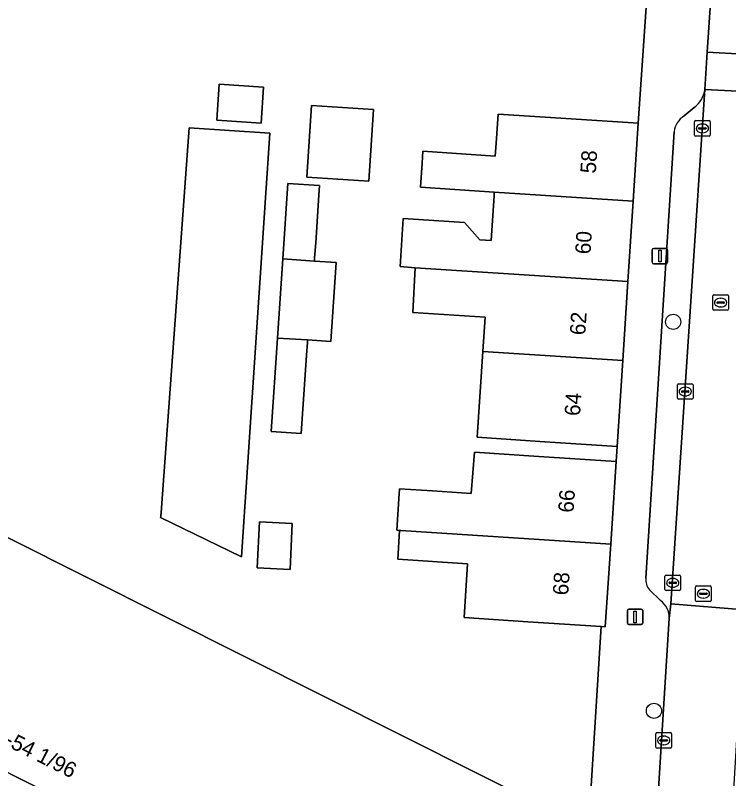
# Model space of a CAD drawing. Extents: x 160349 to 161355, y 381727 to 382854.
# Drawn here: x 160480.68 to 160526.67, y 382016.9 to 382066.09 of the extents above; entities that cross this region are included whole.
import ezdxf

# ---------------------------------------------------------------- set-up
doc = ezdxf.new("R2010")
doc.units = 0
for name, color, linetype in [('IMGEO_Boom', 7, 'Continuous'), ('IMGEO_Erf', 7, 'Continuous'), ('IMGEO_Kolk', 7, 'Continuous'), ('IMGEO_Lichtmast', 7, 'Continuous'), ('IMGEO_Pand', 7, 'Continuous'), ('IMGEO_Pand_nummerreeks', 7, 'Continuous'), ('IMGEO_Parkeervlak_open', 7, 'Continuous'), ('IMGEO_Rijbaan_lokaal_open', 7, 'Continuous'), ('IMGEO_Rioolput', 7, 'Continuous'), ('IMGEO_Voetpad_open', 7, 'Continuous')]:
    doc.layers.add(name, color=color, linetype=linetype)

msp = doc.modelspace()

# ---------------------------------------------------------------- linework, layer by layer
at = {"layer": 'IMGEO_Boom'}
for centre in [(160523.087, 382046.336), (160521.848, 382021.271)]:
    msp.add_circle(centre, 0.489, dxfattribs=at)
at = {"layer": 'IMGEO_Erf'}
msp.add_lwpolyline([(160517.469, 382011.278), (160518.446, 382026.709), (160513.722, 382027.017), (160509.607, 382027.278), (160509.82, 382030.754), (160505.333, 382031.047), (160505.456, 382032.902), (160505.273, 382032.914), (160505.426, 382035.282), (160505.442, 382035.525), (160505.446, 382035.586), (160507.584, 382035.446), (160510.075, 382035.283), (160510.286, 382037.948), (160514.417, 382037.667), (160519.406, 382037.341), (160519.474, 382038.309), (160514.485, 382038.635), (160510.455, 382038.898), (160510.816, 382044.432), (160510.96, 382046.638), (160506.3, 382046.943), (160506.464, 382049.826), (160505.491, 382049.898), (160505.694, 382052.997), (160509.639, 382052.739), (160510.616, 382051.626), (160511.351, 382051.578), (160511.539, 382054.465), (160511.554, 382054.702), (160506.797, 382055.012), (160506.898, 382056.555), (160506.948, 382057.327), (160511.622, 382057.02), (160511.676, 382057.846), (160511.799, 382059.731), (160515.844, 382059.467), (160520.833, 382059.141), (160521.557, 382069.746)], dxfattribs=at)
for points in [[(160479.916, 382059.863), (160466.35, 382032.89), (160472.463, 382029.821), (160475.062, 382034.999), (160515.732, 382014.582), (160512.424, 382007.997), (160513.909, 382007.227), (160510.392, 382000.227), (160508.55, 382001.159), (160509.315, 382002.675), (160460.202, 382027.329), (160459.424, 382025.758), (160454.11, 382028.419), (160455.535, 382031.265), (160457.345, 382034.882), (160453.202, 382036.961), (160467.763, 382065.943), (160466.417, 382066.617), (160467.478, 382068.699), (160475.537, 382064.67), (160474.49, 382062.578)], [(160496.69, 382061.467), (160496.533, 382059.132), (160493.675, 382059.324), (160493.832, 382061.659)], [(160503.771, 382060.023), (160503.47, 382055.395), (160499.47, 382055.654), (160499.771, 382060.283)], [(160497.082, 382058.494), (160495.27, 382031.193), (160495.214, 382031.22), (160490.053, 382033.734), (160490.059, 382033.81), (160490.077, 382034.058), (160491.886, 382058.843)], [(160497.929, 382050.391), (160498.261, 382055.25), (160500.299, 382055.124), (160500.257, 382054.512), (160500.047, 382051.439), (160499.98, 382050.456), (160499.966, 382050.258), (160501.368, 382050.167), (160501.019, 382045.071), (160499.524, 382045.169), (160499.512, 382045.003), (160499.457, 382044.2), (160499.111, 382039.145), (160497.168, 382039.271), (160497.58, 382045.296)], [(160496.422, 382033.455), (160498.54, 382033.353), (160498.396, 382030.379), (160496.279, 382030.481)]]:
    msp.add_lwpolyline(points, close=True, dxfattribs=at)
at = {"layer": 'IMGEO_Kolk'}
for p, q in [((160524.543, 382059.304), (160525.395, 382059.304)), ((160524.468, 382058.378), (160524.468, 382059.23)), ((160524.77, 382058.847), (160525.168, 382058.847)), ((160524.956, 382059.084), (160524.981, 382059.084)), ((160525.469, 382059.23), (160525.469, 382058.378)), ((160524.727, 382058.798), (160524.727, 382058.81)), ((160525.165, 382058.761), (160524.767, 382058.761)), ((160524.979, 382058.524), (160524.954, 382058.524)), ((160525.211, 382058.81), (160525.211, 382058.798)), ((160525.395, 382058.304), (160524.543, 382058.304)), ((160523.362, 382041.421), (160523.362, 382042.273)), ((160523.437, 382042.347), (160524.289, 382042.347)), ((160523.85, 382042.127), (160523.875, 382042.127)), ((160524.363, 382042.273), (160524.363, 382041.421)), ((160523.621, 382041.841), (160523.621, 382041.853)), ((160524.059, 382041.804), (160523.661, 382041.804)), ((160523.664, 382041.89), (160524.062, 382041.89)), ((160524.105, 382041.853), (160524.105, 382041.841)), ((160524.289, 382041.347), (160523.437, 382041.347)), ((160523.873, 382041.567), (160523.848, 382041.567)), ((160522.557, 382029.095), (160522.557, 382029.947)), ((160522.632, 382030.021), (160523.484, 382030.021)), ((160523.045, 382029.801), (160523.07, 382029.801)), ((160523.558, 382029.947), (160523.558, 382029.095)), ((160522.816, 382029.515), (160522.816, 382029.527)), ((160523.254, 382029.478), (160522.856, 382029.478)), ((160522.859, 382029.564), (160523.257, 382029.564)), ((160523.3, 382029.527), (160523.3, 382029.515)), ((160523.484, 382029.021), (160522.632, 382029.021)), ((160523.068, 382029.241), (160523.043, 382029.241)), ((160521.975, 382018.94), (160521.975, 382019.792)), ((160522.05, 382019.866), (160522.902, 382019.866)), ((160522.463, 382019.646), (160522.488, 382019.646)), ((160522.976, 382019.792), (160522.976, 382018.94)), ((160522.234, 382019.36), (160522.234, 382019.372)), ((160522.672, 382019.323), (160522.274, 382019.323)), ((160522.277, 382019.409), (160522.675, 382019.409)), ((160522.486, 382019.086), (160522.461, 382019.086)), ((160522.718, 382019.372), (160522.718, 382019.36)), ((160522.902, 382018.866), (160522.05, 382018.866))]:
    msp.add_line(p, q, dxfattribs=at)
for points in [[(160524.543, 382059.304), (160525.395, 382059.304)], [(160524.468, 382058.378), (160524.468, 382059.23)], [(160525.469, 382059.23), (160525.469, 382058.378)], [(160525.395, 382058.304), (160524.543, 382058.304)], [(160523.362, 382041.421), (160523.362, 382042.273)], [(160523.437, 382042.347), (160524.289, 382042.347)], [(160524.363, 382042.273), (160524.363, 382041.421)], [(160524.289, 382041.347), (160523.437, 382041.347)], [(160522.557, 382029.095), (160522.557, 382029.947)], [(160522.632, 382030.021), (160523.484, 382030.021)], [(160523.558, 382029.947), (160523.558, 382029.095)], [(160523.484, 382029.021), (160522.632, 382029.021)], [(160521.975, 382018.94), (160521.975, 382019.792)], [(160522.05, 382019.866), (160522.902, 382019.866)], [(160522.976, 382019.792), (160522.976, 382018.94)], [(160522.902, 382018.866), (160522.05, 382018.866)]]:
    msp.add_lwpolyline(points, dxfattribs=at)
for centre, radius, start, end in [((160524.545, 382059.228), 0.0765, 91.552, 178.448), ((160524.545, 382059.228), 0.0765, 91.552, 178.448), ((160525.393, 382059.228), 0.0765, 1.552, 88.448), ((160525.393, 382059.228), 0.0765, 1.552, 88.448), ((160524.767, 382058.807), 0.0403, 85.8775, 175.7526), ((160525.172, 382058.809), 0.0386, 1.7309, 96.639), ((160524.545, 382058.38), 0.0765, 181.552, 268.448), ((160524.545, 382058.38), 0.0765, 181.552, 268.448), ((160524.764, 382058.797), 0.0366, 178.938, 274.7102), ((160525.168, 382058.804), 0.043, 264.8664, 352.4533), ((160525.393, 382058.38), 0.0765, 271.552, 358.448), ((160525.393, 382058.38), 0.0765, 271.552, 358.448), ((160523.439, 382042.271), 0.0765, 91.552, 178.448), ((160523.439, 382042.271), 0.0765, 91.552, 178.448), ((160524.287, 382042.271), 0.0765, 1.552, 88.448), ((160524.287, 382042.271), 0.0765, 1.552, 88.448), ((160523.661, 382041.85), 0.0403, 85.8775, 175.7526), ((160523.658, 382041.84), 0.0366, 178.938, 274.7102), ((160524.062, 382041.847), 0.043, 264.8664, 352.4533), ((160524.066, 382041.852), 0.0386, 1.7309, 96.639), ((160523.439, 382041.423), 0.0765, 181.552, 268.448), ((160523.439, 382041.423), 0.0765, 181.552, 268.448), ((160524.287, 382041.423), 0.0765, 271.552, 358.448), ((160524.287, 382041.423), 0.0765, 271.552, 358.448), ((160522.634, 382029.945), 0.0765, 91.552, 178.448), ((160522.634, 382029.945), 0.0765, 91.552, 178.448), ((160523.482, 382029.945), 0.0765, 1.552, 88.448), ((160523.482, 382029.945), 0.0765, 1.552, 88.448), ((160522.856, 382029.524), 0.0403, 85.8775, 175.7526), ((160522.853, 382029.514), 0.0366, 178.938, 274.7102), ((160523.257, 382029.521), 0.043, 264.8664, 352.4533), ((160523.261, 382029.526), 0.0386, 1.7309, 96.639), ((160522.634, 382029.097), 0.0765, 181.552, 268.448), ((160522.634, 382029.097), 0.0765, 181.552, 268.448), ((160523.482, 382029.097), 0.0765, 271.552, 358.448), ((160523.482, 382029.097), 0.0765, 271.552, 358.448), ((160522.052, 382019.79), 0.0765, 91.552, 178.448), ((160522.052, 382019.79), 0.0765, 91.552, 178.448), ((160522.9, 382019.79), 0.0765, 1.552, 88.448), ((160522.9, 382019.79), 0.0765, 1.552, 88.448), ((160522.274, 382019.369), 0.0403, 85.8775, 175.7526), ((160522.271, 382019.359), 0.0366, 178.938, 274.7102), ((160522.675, 382019.366), 0.043, 264.8664, 352.4533), ((160522.679, 382019.371), 0.0386, 1.7309, 96.639), ((160522.052, 382018.942), 0.0765, 181.552, 268.448), ((160522.052, 382018.942), 0.0765, 181.552, 268.448), ((160522.9, 382018.942), 0.0765, 271.552, 358.448), ((160522.9, 382018.942), 0.0765, 271.552, 358.448)]:
    msp.add_arc(centre, radius, start, end, dxfattribs=at)
for centre, major_axis, ratio, start_param, end_param in [((160524.955, 382058.804), (-0.387, 0.002), 0.722429, 4.712389, 7.853982), ((160524.98, 382058.804), (-0.39, 0.002), 0.717154, 1.570796, 4.712389), ((160523.849, 382041.847), (-0.387, 0.002), 0.722429, 4.712389, 7.853982), ((160523.874, 382041.847), (-0.39, 0.002), 0.717154, 1.570796, 4.712389), ((160523.044, 382029.521), (-0.387, 0.002), 0.722429, 4.712389, 7.853982), ((160523.069, 382029.521), (-0.39, 0.002), 0.717154, 1.570796, 4.712389), ((160522.462, 382019.366), (-0.387, 0.002), 0.722429, 4.712389, 7.853982), ((160522.487, 382019.366), (-0.39, 0.002), 0.717154, 1.570796, 4.712389)]:
    msp.add_ellipse(centre, major_axis=major_axis, ratio=ratio, start_param=start_param, end_param=end_param, dxfattribs=at)
at = {"layer": 'IMGEO_Lichtmast'}
for p, q in [((160521.732, 382050.174), (160521.732, 382050.974)), ((160521.732, 382050.974), (160521.732, 382050.174)), ((160521.832, 382051.074), (160522.622, 382051.074)), ((160522.622, 382051.074), (160521.832, 382051.074)), ((160522.722, 382050.974), (160522.722, 382050.174)), ((160522.722, 382050.174), (160522.722, 382050.974)), ((160522.622, 382050.074), (160521.832, 382050.074)), ((160521.832, 382050.074), (160522.622, 382050.074)), ((160520.234, 382027.828), (160521.024, 382027.828)), ((160521.024, 382027.828), (160520.234, 382027.828)), ((160520.134, 382026.928), (160520.134, 382027.728)), ((160520.134, 382027.728), (160520.134, 382026.928)), ((160521.124, 382027.728), (160521.124, 382026.928)), ((160521.124, 382026.928), (160521.124, 382027.728)), ((160521.024, 382026.828), (160520.234, 382026.828)), ((160520.234, 382026.828), (160521.024, 382026.828))]:
    msp.add_line(p, q, dxfattribs=at)
for points in [[(160522.152, 382050.949), (160522.302, 382050.949), (160522.302, 382050.199), (160522.152, 382050.199), (160522.152, 382050.949)], [(160520.554, 382027.703), (160520.704, 382027.703), (160520.704, 382026.953), (160520.554, 382026.953), (160520.554, 382027.703)]]:
    msp.add_lwpolyline(points, dxfattribs=at)
for centre, start, end in [((160521.832, 382050.974), 90, 180), ((160521.832, 382050.974), 90, 180), ((160522.622, 382050.974), 0, 90), ((160522.622, 382050.974), 360, 90), ((160521.832, 382050.174), 180, 270), ((160521.832, 382050.174), 180, 270), ((160522.622, 382050.174), 270, 0), ((160522.622, 382050.174), 270, 0), ((160520.234, 382027.728), 90, 180), ((160520.234, 382027.728), 90, 180), ((160521.024, 382027.728), 0, 90), ((160521.024, 382027.728), 360, 90), ((160520.234, 382026.928), 180, 270), ((160520.234, 382026.928), 180, 270), ((160521.024, 382026.928), 270, 0), ((160521.024, 382026.928), 270, 0)]:
    msp.add_arc(centre, 0.1, start, end, dxfattribs=at)
at = {"layer": 'IMGEO_Pand'}
for points in [[(160475.062, 382034.999), (160472.463, 382029.821), (160466.35, 382032.89), (160479.916, 382059.863), (160474.49, 382062.578), (160467.763, 382065.943), (160453.202, 382036.961), (160457.345, 382034.882), (160455.535, 382031.265), (160454.11, 382028.419), (160459.424, 382025.758), (160460.202, 382027.329), (160509.315, 382002.675), (160509.662, 382002.5), (160512.424, 382007.997), (160515.732, 382014.582)], [(160496.69, 382061.467), (160493.832, 382061.659), (160493.675, 382059.324), (160496.533, 382059.132)], [(160503.771, 382060.023), (160499.771, 382060.283), (160499.47, 382055.654), (160503.47, 382055.395)], [(160520.833, 382059.141), (160515.844, 382059.467), (160511.799, 382059.731), (160511.676, 382057.846), (160511.622, 382057.02), (160506.948, 382057.327), (160506.898, 382056.555), (160506.797, 382055.012), (160511.554, 382054.702), (160520.505, 382054.118)], [(160490.059, 382033.81), (160490.053, 382033.734), (160495.214, 382031.22), (160495.27, 382031.193), (160497.082, 382058.494), (160491.886, 382058.843), (160490.077, 382034.058)], [(160497.929, 382050.391), (160499.966, 382050.258), (160499.98, 382050.456), (160500.047, 382051.439), (160500.257, 382054.512), (160500.299, 382055.124), (160498.261, 382055.25)], [(160520.505, 382054.118), (160511.554, 382054.702), (160511.539, 382054.465), (160511.351, 382051.578), (160510.616, 382051.626), (160509.639, 382052.739), (160505.694, 382052.997), (160505.491, 382049.898), (160506.464, 382049.826), (160520.168, 382048.94)], [(160499.966, 382050.258), (160497.929, 382050.391), (160497.58, 382045.296), (160499.524, 382045.169), (160501.019, 382045.071), (160501.368, 382050.167)], [(160506.3, 382046.943), (160510.96, 382046.638), (160510.816, 382044.432), (160519.835, 382043.843), (160520.168, 382048.94), (160506.464, 382049.826)], [(160499.524, 382045.169), (160497.58, 382045.296), (160497.168, 382039.271), (160499.111, 382039.145), (160499.457, 382044.2), (160499.512, 382045.003)], [(160519.835, 382043.843), (160510.816, 382044.432), (160510.455, 382038.898), (160514.485, 382038.635), (160519.474, 382038.309)], [(160519.406, 382037.341), (160514.417, 382037.667), (160510.286, 382037.948), (160510.075, 382035.283), (160507.584, 382035.446), (160505.446, 382035.586), (160505.442, 382035.525), (160505.426, 382035.282), (160505.273, 382032.914), (160505.456, 382032.902), (160505.54, 382032.896), (160519.058, 382032.015)], [(160496.422, 382033.455), (160496.279, 382030.481), (160498.396, 382030.379), (160498.54, 382033.353)], [(160519.058, 382032.015), (160505.54, 382032.896), (160505.456, 382032.902), (160505.333, 382031.047), (160509.82, 382030.754), (160509.607, 382027.278), (160513.722, 382027.017), (160518.446, 382026.709), (160518.711, 382026.692)]]:
    msp.add_lwpolyline(points, close=True, dxfattribs=at)
at = {"layer": 'IMGEO_Parkeervlak_open'}
for points in [[(160522.929, 382028.173), (160525.134, 382061.313)], [(160524.433, 382060.14), (160523.786, 382059.607)], [(160523.15, 382058.591), (160521.324, 382029.829)], [(160521.555, 382029.07), (160522.263, 382028.374)], [(160522.836, 382027.224), (160522.929, 382028.173)]]:
    msp.add_lwpolyline(points, dxfattribs=at)
for centre, radius, start, end in [((160523.365, 382061.574), 1.788, 306.6775, 351.5964), ((160524.521, 382058.44), 1.379, 122.1914, 173.7168), ((160522.294, 382029.709), 0.977, 172.9752, 220.8798), ((160521.425, 382027.239), 1.411, 359.4003, 53.5703)]:
    msp.add_arc(centre, radius, start, end, dxfattribs=at)
at = {"layer": 'IMGEO_Rijbaan_lokaal_open'}
for points in [[(160525.275, 382063.726), (160529.962, 382063.456), (160530.734, 382074.953), (160526.048, 382075.185)], [(160525.134, 382061.313), (160529.795, 382061.08), (160529.962, 382063.456), (160525.275, 382063.726)], [(160528.807, 382045.931), (160529.795, 382061.08), (160525.134, 382061.313), (160522.929, 382028.173), (160527.69, 382027.78), (160528.002, 382032.642), (160528.662, 382043.535)]]:
    msp.add_lwpolyline(points, close=True, dxfattribs=at)
msp.add_lwpolyline([(160526.719, 382011.433), (160527.69, 382027.78), (160522.929, 382028.173), (160522.836, 382027.224), (160521.895, 382012.476), (160521.512, 382011.289), (160519.525, 382006.044), (160514.813, 381996.196), (160514.455, 381995.447)], dxfattribs=at)
at = {"layer": 'IMGEO_Rioolput'}
for p, q in [((160525.641, 382047.155), (160525.641, 382048.007)), ((160525.716, 382048.081), (160526.568, 382048.081)), ((160526.642, 382048.007), (160526.642, 382047.155)), ((160525.9, 382047.575), (160525.9, 382047.587)), ((160526.338, 382047.538), (160525.94, 382047.538)), ((160525.943, 382047.624), (160526.341, 382047.624)), ((160526.129, 382047.861), (160526.154, 382047.861)), ((160526.384, 382047.587), (160526.384, 382047.575)), ((160526.568, 382047.081), (160525.716, 382047.081)), ((160526.152, 382047.301), (160526.127, 382047.301)), ((160524.608, 382029.318), (160525.46, 382029.318)), ((160524.533, 382028.392), (160524.533, 382029.244)), ((160524.792, 382028.812), (160524.792, 382028.824)), ((160524.835, 382028.861), (160525.233, 382028.861)), ((160525.021, 382029.098), (160525.046, 382029.098)), ((160525.276, 382028.824), (160525.276, 382028.812)), ((160525.534, 382029.244), (160525.534, 382028.392)), ((160525.46, 382028.318), (160524.608, 382028.318)), ((160525.23, 382028.775), (160524.832, 382028.775)), ((160525.044, 382028.538), (160525.019, 382028.538))]:
    msp.add_line(p, q, dxfattribs=at)
for points in [[(160525.641, 382047.155), (160525.641, 382048.007)], [(160525.716, 382048.081), (160526.568, 382048.081)], [(160526.642, 382048.007), (160526.642, 382047.155)], [(160526.568, 382047.081), (160525.716, 382047.081)], [(160524.608, 382029.318), (160525.46, 382029.318)], [(160524.533, 382028.392), (160524.533, 382029.244)], [(160525.534, 382029.244), (160525.534, 382028.392)], [(160525.46, 382028.318), (160524.608, 382028.318)]]:
    msp.add_lwpolyline(points, dxfattribs=at)
for centre, radius, start, end in [((160525.718, 382048.005), 0.0765, 91.552, 178.448), ((160525.718, 382048.005), 0.0765, 91.552, 178.448), ((160526.566, 382048.005), 0.0765, 1.552, 88.448), ((160526.566, 382048.005), 0.0765, 1.552, 88.448), ((160525.94, 382047.584), 0.0403, 85.8775, 175.7526), ((160525.937, 382047.574), 0.0366, 178.938, 274.7102), ((160526.341, 382047.581), 0.043, 264.8664, 352.4533), ((160526.345, 382047.586), 0.0386, 1.7309, 96.639), ((160525.718, 382047.157), 0.0765, 181.552, 268.448), ((160525.718, 382047.157), 0.0765, 181.552, 268.448), ((160526.566, 382047.157), 0.0765, 271.552, 358.448), ((160526.566, 382047.157), 0.0765, 271.552, 358.448), ((160524.61, 382029.242), 0.0765, 91.552, 178.448), ((160524.61, 382029.242), 0.0765, 91.552, 178.448), ((160525.458, 382029.242), 0.0765, 1.552, 88.448), ((160525.458, 382029.242), 0.0765, 1.552, 88.448), ((160524.832, 382028.821), 0.0403, 85.8775, 175.7526), ((160524.829, 382028.811), 0.0366, 178.938, 274.7102), ((160525.233, 382028.818), 0.043, 264.8664, 352.4533), ((160525.237, 382028.823), 0.0386, 1.7309, 96.639), ((160524.61, 382028.394), 0.0765, 181.552, 268.448), ((160524.61, 382028.394), 0.0765, 181.552, 268.448), ((160525.458, 382028.394), 0.0765, 271.552, 358.448), ((160525.458, 382028.394), 0.0765, 271.552, 358.448)]:
    msp.add_arc(centre, radius, start, end, dxfattribs=at)
for centre, major_axis, ratio, start_param, end_param in [((160526.128, 382047.581), (-0.387, 0.002), 0.722429, 4.712389, 7.853982), ((160526.153, 382047.581), (-0.39, 0.002), 0.717154, 1.570796, 4.712389), ((160525.02, 382028.818), (-0.387, 0.002), 0.722429, 4.712389, 7.853982), ((160525.045, 382028.818), (-0.39, 0.002), 0.717154, 1.570796, 4.712389)]:
    msp.add_ellipse(centre, major_axis=major_axis, ratio=ratio, start_param=start_param, end_param=end_param, dxfattribs=at)
at = {"layer": 'IMGEO_Voetpad_open'}
for points in [[(160525.134, 382061.313), (160525.275, 382063.726), (160526.048, 382075.185), (160526.177, 382077.688), (160526.212, 382078.198)], [(160521.557, 382069.746), (160520.833, 382059.141), (160520.505, 382054.118), (160520.168, 382048.94), (160519.835, 382043.843), (160519.474, 382038.309), (160519.406, 382037.341), (160519.058, 382032.015), (160518.711, 382026.692), (160518.446, 382026.709), (160517.469, 382011.278)], [(160523.786, 382059.607), (160524.433, 382060.14)], [(160521.324, 382029.829), (160523.15, 382058.591)], [(160522.263, 382028.374), (160521.555, 382029.07)], [(160508.456, 381999.148), (160514.813, 381996.196), (160519.525, 382006.044), (160521.512, 382011.289), (160521.895, 382012.476), (160522.836, 382027.224)]]:
    msp.add_lwpolyline(points, dxfattribs=at)
for centre, radius, start, end in [((160523.365, 382061.574), 1.788, 306.6775, 351.5964), ((160524.521, 382058.44), 1.379, 122.1914, 173.7168), ((160522.294, 382029.709), 0.977, 172.9752, 220.8798), ((160521.425, 382027.239), 1.411, 359.4003, 53.5703)]:
    msp.add_arc(centre, radius, start, end, dxfattribs=at)

# ---------------------------------------------------------------- texts
at = {"layer": 'IMGEO_Pand_nummerreeks'}
for s, rotation, p in [('58', 86.2703, (160518.095, 382055.88)), ('60', 86.2703, (160517.756, 382050.672)), ('62', 86.2675, (160517.416, 382045.458)), ('64', 86.2675, (160517.076, 382040.253)), ('66', 86.2645, (160516.664, 382034.019)), ('68', 86.2645, (160516.317, 382028.697)), ('54-54 1/96', 333.346, (160478.596, 382019.773))]:
    msp.add_text(s, height=1, rotation=rotation, dxfattribs=at).set_placement(p)

doc.saveas('drawing.dxf')
